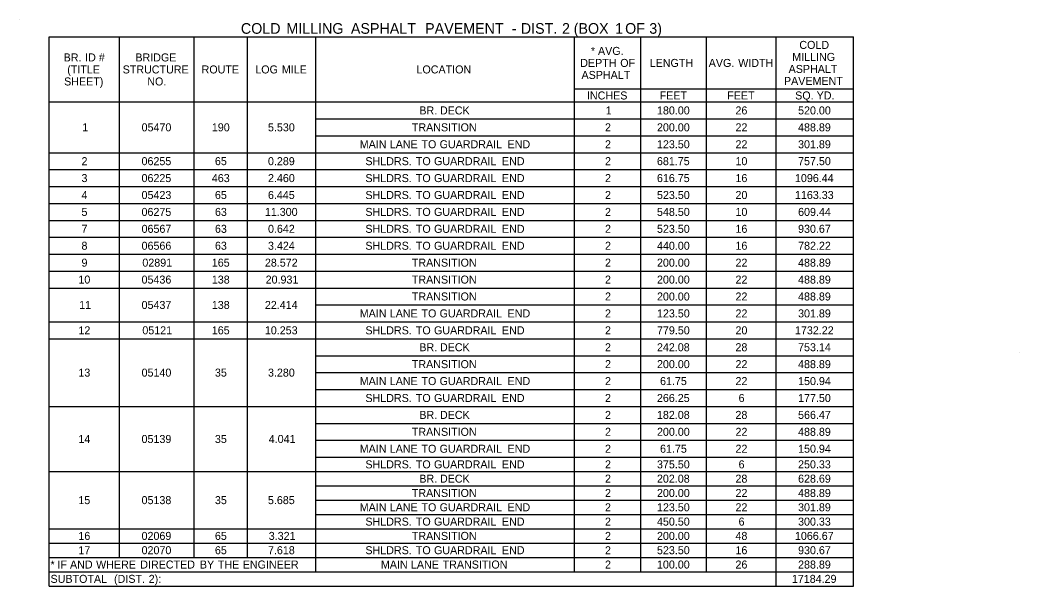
# Model space of a CAD drawing. Extents: x 544250 to 1930787, y -1948365 to 596640.
# Drawn here: x 548053 to 548802, y -1947842 to -1947418 of the extents above; entities that cross this region are included whole.
import ezdxf

# ---------------------------------------------------------------- set-up
doc = ezdxf.new("R2010")
doc.units = 0
doc.layers.add('Default', color=7, linetype='Continuous')

msp = doc.modelspace()

# ---------------------------------------------------------------- linework, layer by layer
at = {"layer": 'Default'}
for p, q in [((548053.38, -1947417.61), (548053.38, -1947417.61)), ((548075.32, -1947430.28), (548678.35, -1947430.28)), ((548075.32, -1947430.28), (548678.35, -1947430.28)), ((548075.32, -1947841.73), (548075.32, -1947430.28)), ((548075.32, -1947841.73), (548075.32, -1947430.28)), ((548127.97, -1947820.28), (548127.97, -1947430.28)), ((548184.03, -1947820.28), (548184.03, -1947430.28)), ((548224, -1947820.28), (548224, -1947430.28)), ((548275.19, -1947831.01), (548275.19, -1947430.28)), ((548469.22, -1947831.01), (548469.22, -1947430.28)), ((548518.94, -1947831.01), (548518.94, -1947430.28)), ((548568.18, -1947831.01), (548568.18, -1947430.28)), ((548620.34, -1947841.73), (548620.34, -1947430.28)), ((548678.35, -1947841.73), (548678.35, -1947430.28)), ((548469.22, -1947469.28), (548568.18, -1947469.28)), ((548469.22, -1947469.28), (548518.94, -1947469.28)), ((548518.94, -1947469.28), (548678.35, -1947469.28)), ((548568.18, -1947479.03), (548568.18, -1947469.28)), ((548075.32, -1947479.03), (548678.35, -1947479.03)), ((548275.19, -1947491.71), (548678.35, -1947491.71)), ((548275.19, -1947504.38), (548678.35, -1947504.38)), ((548075.32, -1947517.06), (548678.35, -1947517.06)), ((548275.19, -1947517.06), (548678.35, -1947517.06)), ((548075.32, -1947529.73), (548678.35, -1947529.73)), ((548469.22, -1947529.73), (548678.35, -1947529.73)), ((548075.32, -1947542.41), (548678.35, -1947542.41)), ((548075.32, -1947555.08), (548678.35, -1947555.08)), ((548075.32, -1947567.76), (548678.35, -1947567.76)), ((548075.32, -1947580.43), (548678.35, -1947580.43)), ((548075.32, -1947593.11), (548678.35, -1947593.11)), ((548075.32, -1947605.78), (548678.35, -1947605.78)), ((548075.32, -1947618.46), (548678.35, -1947618.46)), ((548275.19, -1947631.13), (548678.35, -1947631.13)), ((548075.32, -1947643.81), (548678.35, -1947643.81)), ((548075.32, -1947656.48), (548678.35, -1947656.48)), ((548275.19, -1947669.16), (548678.35, -1947669.16)), ((548802.37, -1947666.61), (548802.37, -1947666.61)), ((548275.19, -1947681.83), (548678.35, -1947681.83)), ((548275.19, -1947694.51), (548678.35, -1947694.51)), ((548518.94, -1947694.51), (548620.34, -1947694.51)), ((548620.34, -1947694.51), (548678.35, -1947694.51)), ((548075.32, -1947707.18), (548678.35, -1947707.18)), ((548275.19, -1947719.86), (548678.35, -1947719.86)), ((548275.19, -1947732.53), (548678.35, -1947732.53)), ((548275.19, -1947745.21), (548678.35, -1947745.21)), ((548518.94, -1947745.21), (548620.34, -1947745.21)), ((548620.34, -1947745.21), (548678.35, -1947745.21)), ((548075.32, -1947755.93), (548678.35, -1947755.93)), ((548275.19, -1947766.66), (548678.35, -1947766.66)), ((548275.19, -1947777.38), (548678.35, -1947777.38)), ((548275.19, -1947788.11), (548678.35, -1947788.11)), ((548275.19, -1947788.11), (548678.35, -1947788.11)), ((548075.32, -1947798.83), (548678.35, -1947798.83)), ((548075.32, -1947809.56), (548275.19, -1947809.56)), ((548275.19, -1947809.56), (548678.35, -1947809.56)), ((548075.32, -1947820.28), (548678.35, -1947820.28)), ((548620.34, -1947820.28), (548678.35, -1947820.28)), ((548075.32, -1947831.01), (548678.35, -1947831.01)), ((548075.32, -1947841.73), (548678.35, -1947841.73))]:
    msp.add_line(p, q, dxfattribs=at)

# ---------------------------------------------------------------- texts
for s, height, p in [('COLD', 8, (548219.01, -1947427.94)), (' MILLING', 8, (548250.12, -1947427.94)), (' ASPHALT', 8, (548298.5, -1947427.94)), (' PAVEMENT', 8, (548354.16, -1947427.94)), (' -', 8, (548419.15, -1947427.94)), (' DIST.', 8, (548425.89, -1947427.94)), (' 2', 8, (548456.79, -1947427.94)), (' (BOX', 8, (548465.55, -1947427.94)), (' 1', 8, (548496.59, -1947427.94)), (' OF', 8, (548504.09, -1947427.94)), (' 3)', 8, (548522.2, -1947427.94)), ('COLD', 6, (548637.68, -1947439.28)), ('*', 6, (548481.41, -1947443.78)), (' AVG.', 6, (548484.49, -1947443.78)), ('BR.', 6, (548086.12, -1947448.66)), (' ID', 6, (548099.98, -1947448.66)), (' #', 6, (548110.27, -1947448.66)), ('BRIDGE', 6, (548139.9, -1947448.66)), ('DEPTH', 6, (548473.4, -1947452.78)), (' OF', 6, (548501.17, -1947452.78)), ('LENGTH', 6, (548525.48, -1947452.78)), ('AVG.', 6, (548569.72, -1947452.78)), (' WIDTH', 6, (548589.64, -1947452.78)), ('MILLING', 6, (548632.37, -1947448.28)), ('(TITLE', 6, (548088.81, -1947457.66)), ('STRUCTURE', 6, (548130.35, -1947457.66)), ('ROUTE', 6, (548189.55, -1947457.66)), ('LOG', 6, (548229.8, -1947457.66)), (' MILE', 6, (548247.46, -1947457.66)), ('LOCATION', 6, (548350.65, -1947457.66)), ('ASPHALT', 6, (548474.37, -1947461.78)), ('ASPHALT', 6, (548629.64, -1947457.28)), ('SHEET)', 6, (548086.48, -1947466.66)), ('NO.', 6, (548148.83, -1947466.66)), ('PAVEMENT', 6, (548626.14, -1947466.28)), ('INCHES', 6, (548478.44, -1947477.16)), ('FEET', 6, (548532.93, -1947477.16)), ('FEET', 6, (548583.63, -1947477.16)), ('SQ.', 6, (548634.55, -1947477.16)), (' YD.', 6, (548648.42, -1947477.16)), ('BR.', 6, (548352.78, -1947488.37)), (' DECK', 6, (548366.02, -1947488.37)), ('1', 6, (548492.52, -1947488.37)), ('180.00', 6, (548530.95, -1947488.37)), ('26', 6, (548589.79, -1947488.37)), ('520.00', 6, (548636.73, -1947488.37)), ('1', 6, (548100.08, -1947501.04)), ('05470', 6, (548144.55, -1947501.04)), ('190', 6, (548197.23, -1947501.04)), ('5.530', 6, (548239.31, -1947501.04)), ('TRANSITION', 6, (548347.16, -1947501.04)), ('2', 6, (548491.97, -1947501.04)), ('200.00', 6, (548530.95, -1947501.04)), ('22', 6, (548589.82, -1947501.04)), ('488.89', 6, (548636.72, -1947501.04)), ('MAIN', 6, (548308.11, -1947513.72)), (' LANE', 6, (548328.39, -1947513.72)), (' TO', 6, (548352.17, -1947513.72)), (' GUARDRAIL', 6, (548365.76, -1947513.72)), (' END', 6, (548416.71, -1947513.72)), ('2', 6, (548491.97, -1947513.72)), ('123.50', 6, (548530.95, -1947513.72)), ('22', 6, (548589.82, -1947513.72)), ('301.89', 6, (548636.72, -1947513.72)), ('2', 6, (548099.53, -1947526.39)), ('06255', 6, (548144.51, -1947526.39)), ('65', 6, (548199.52, -1947526.39)), ('0.289', 6, (548239.3, -1947526.39)), ('SHLDRS.', 6, (548312.34, -1947526.39)), (' TO', 6, (548347.94, -1947526.39)), (' GUARDRAIL', 6, (548361.54, -1947526.39)), (' END', 6, (548412.49, -1947526.39)), ('2', 6, (548491.97, -1947526.39)), ('681.75', 6, (548530.91, -1947526.39)), ('10', 6, (548589.8, -1947526.39)), ('757.50', 6, (548636.73, -1947526.39)), ('3', 6, (548099.5, -1947539.07)), ('06225', 6, (548144.51, -1947539.07)), ('463', 6, (548197.22, -1947539.07)), ('2.460', 6, (548239.31, -1947539.07)), ('SHLDRS.', 6, (548312.34, -1947539.07)), (' TO', 6, (548347.94, -1947539.07)), (' GUARDRAIL', 6, (548361.54, -1947539.07)), (' END', 6, (548412.49, -1947539.07)), ('2', 6, (548491.97, -1947539.07)), ('616.75', 6, (548530.91, -1947539.07)), ('16', 6, (548589.79, -1947539.07)), ('1096.44', 6, (548634.41, -1947539.07)), ('4', 6, (548099.51, -1947551.74)), ('05423', 6, (548144.54, -1947551.74)), ('65', 6, (548199.52, -1947551.74)), ('6.445', 6, (548239.28, -1947551.74)), ('SHLDRS.', 6, (548312.34, -1947551.74)), (' TO', 6, (548347.94, -1947551.74)), (' GUARDRAIL', 6, (548361.54, -1947551.74)), (' END', 6, (548412.49, -1947551.74)), ('2', 6, (548491.97, -1947551.74)), ('523.50', 6, (548530.95, -1947551.74)), ('20', 6, (548589.8, -1947551.74)), ('1163.33', 6, (548634.39, -1947551.74)), ('5', 6, (548099.48, -1947564.42)), ('06275', 6, (548144.51, -1947564.42)), ('63', 6, (548199.55, -1947564.42)), ('11.300', 6, (548236.98, -1947564.42)), ('SHLDRS.', 6, (548312.34, -1947564.42)), (' TO', 6, (548347.94, -1947564.42)), (' GUARDRAIL', 6, (548361.54, -1947564.42)), (' END', 6, (548412.49, -1947564.42)), ('2', 6, (548491.97, -1947564.42)), ('548.50', 6, (548530.95, -1947564.42)), ('10', 6, (548589.8, -1947564.42)), ('609.44', 6, (548636.74, -1947564.42)), ('7', 6, (548099.5, -1947577.09)), ('06567', 6, (548144.54, -1947577.09)), ('63', 6, (548199.55, -1947577.09)), ('0.642', 6, (548239.33, -1947577.09)), ('SHLDRS.', 6, (548312.34, -1947577.09)), (' TO', 6, (548347.94, -1947577.09)), (' GUARDRAIL', 6, (548361.54, -1947577.09)), (' END', 6, (548412.49, -1947577.09)), ('2', 6, (548491.97, -1947577.09)), ('523.50', 6, (548530.95, -1947577.09)), ('16', 6, (548589.79, -1947577.09)), ('930.67', 6, (548636.72, -1947577.09)), ('8', 6, (548099.5, -1947589.77)), ('06566', 6, (548144.54, -1947589.77)), ('63', 6, (548199.55, -1947589.77)), ('3.424', 6, (548239.32, -1947589.77)), ('SHLDRS.', 6, (548312.34, -1947589.77)), (' TO', 6, (548347.94, -1947589.77)), (' GUARDRAIL', 6, (548361.54, -1947589.77)), (' END', 6, (548412.49, -1947589.77)), ('2', 6, (548491.97, -1947589.77)), ('440.00', 6, (548530.95, -1947589.77)), ('16', 6, (548589.79, -1947589.77)), ('782.22', 6, (548636.75, -1947589.77)), ('9', 6, (548099.5, -1947602.44)), ('02891', 6, (548145.12, -1947602.44)), ('165', 6, (548197.19, -1947602.44)), ('28.572', 6, (548237, -1947602.44)), ('TRANSITION', 6, (548347.16, -1947602.44)), ('2', 6, (548491.97, -1947602.44)), ('200.00', 6, (548530.95, -1947602.44)), ('22', 6, (548589.82, -1947602.44)), ('488.89', 6, (548636.72, -1947602.44)), ('10', 6, (548097.18, -1947615.12)), ('05436', 6, (548144.54, -1947615.12)), ('138', 6, (548197.21, -1947615.12)), ('20.931', 6, (548237.55, -1947615.12)), ('TRANSITION', 6, (548347.16, -1947615.12)), ('2', 6, (548491.97, -1947615.12)), ('200.00', 6, (548530.95, -1947615.12)), ('22', 6, (548589.82, -1947615.12)), ('488.89', 6, (548636.72, -1947615.12)), ('11', 6, (548097.75, -1947634.13)), ('05437', 6, (548144.54, -1947634.13)), ('138', 6, (548197.21, -1947634.13)), ('22.414', 6, (548236.99, -1947634.13)), ('TRANSITION', 6, (548347.16, -1947627.79)), ('2', 6, (548491.97, -1947627.79)), ('200.00', 6, (548530.95, -1947627.79)), ('22', 6, (548589.82, -1947627.79)), ('488.89', 6, (548636.72, -1947627.79)), ('MAIN', 6, (548308.11, -1947640.47)), (' LANE', 6, (548328.39, -1947640.47)), (' TO', 6, (548352.17, -1947640.47)), (' GUARDRAIL', 6, (548365.76, -1947640.47)), (' END', 6, (548416.71, -1947640.47)), ('2', 6, (548491.97, -1947640.47)), ('123.50', 6, (548530.95, -1947640.47)), ('22', 6, (548589.82, -1947640.47)), ('301.89', 6, (548636.72, -1947640.47)), ('12', 6, (548097.2, -1947653.14)), ('05121', 6, (548145.12, -1947653.14)), ('165', 6, (548197.19, -1947653.14)), ('10.253', 6, (548236.97, -1947653.14)), ('SHLDRS.', 6, (548312.34, -1947653.14)), (' TO', 6, (548347.94, -1947653.14)), (' GUARDRAIL', 6, (548361.54, -1947653.14)), (' END', 6, (548412.49, -1947653.14)), ('2', 6, (548491.97, -1947653.14)), ('779.50', 6, (548530.95, -1947653.14)), ('20', 6, (548589.8, -1947653.14)), ('1732.22', 6, (548634.42, -1947653.14)), ('BR.', 6, (548352.78, -1947665.82)), (' DECK', 6, (548366.02, -1947665.82)), ('2', 6, (548491.97, -1947665.82)), ('242.08', 6, (548530.93, -1947665.82)), ('28', 6, (548589.78, -1947665.82)), ('753.14', 6, (548636.74, -1947665.82)), ('TRANSITION', 6, (548347.16, -1947678.49)), ('2', 6, (548491.97, -1947678.49)), ('200.00', 6, (548530.95, -1947678.49)), ('22', 6, (548589.82, -1947678.49)), ('488.89', 6, (548636.72, -1947678.49)), ('13', 6, (548097.17, -1947684.83)), ('05140', 6, (548144.55, -1947684.83)), ('35', 6, (548199.52, -1947684.83)), ('3.280', 6, (548239.31, -1947684.83)), ('MAIN', 6, (548308.11, -1947691.17)), (' LANE', 6, (548328.39, -1947691.17)), (' TO', 6, (548352.17, -1947691.17)), (' GUARDRAIL', 6, (548365.76, -1947691.17)), (' END', 6, (548416.71, -1947691.17)), ('2', 6, (548491.97, -1947691.17)), ('61.75', 6, (548533.24, -1947691.17)), ('22', 6, (548589.82, -1947691.17)), ('150.94', 6, (548636.74, -1947691.17)), ('SHLDRS.', 6, (548312.34, -1947703.84)), (' TO', 6, (548347.94, -1947703.84)), (' GUARDRAIL', 6, (548361.54, -1947703.84)), (' END', 6, (548412.49, -1947703.84)), ('2', 6, (548491.97, -1947703.84)), ('266.25', 6, (548530.91, -1947703.84)), ('6', 6, (548592.12, -1947703.84)), ('177.50', 6, (548636.73, -1947703.84)), ('BR.', 6, (548352.78, -1947716.52)), (' DECK', 6, (548366.02, -1947716.52)), ('2', 6, (548491.97, -1947716.52)), ('182.08', 6, (548530.93, -1947716.52)), ('28', 6, (548589.78, -1947716.52)), ('566.47', 6, (548636.72, -1947716.52)), ('TRANSITION', 6, (548347.16, -1947729.19)), ('2', 6, (548491.97, -1947729.19)), ('200.00', 6, (548530.95, -1947729.19)), ('22', 6, (548589.82, -1947729.19)), ('488.89', 6, (548636.72, -1947729.19)), ('14', 6, (548097.18, -1947734.56)), ('05139', 6, (548144.53, -1947734.56)), ('35', 6, (548199.52, -1947734.56)), ('4.041', 6, (548239.88, -1947734.56)), ('MAIN', 6, (548308.11, -1947741.87)), (' LANE', 6, (548328.39, -1947741.87)), (' TO', 6, (548352.17, -1947741.87)), (' GUARDRAIL', 6, (548365.76, -1947741.87)), (' END', 6, (548416.71, -1947741.87)), ('2', 6, (548491.97, -1947741.87)), ('61.75', 6, (548533.24, -1947741.87)), ('22', 6, (548589.82, -1947741.87)), ('150.94', 6, (548636.74, -1947741.87)), ('SHLDRS.', 6, (548312.34, -1947753.57)), (' TO', 6, (548347.94, -1947753.57)), (' GUARDRAIL', 6, (548361.54, -1947753.57)), (' END', 6, (548412.49, -1947753.57)), ('2', 6, (548491.97, -1947753.57)), ('375.50', 6, (548530.95, -1947753.57)), ('6', 6, (548592.12, -1947753.57)), ('250.33', 6, (548636.72, -1947753.57)), ('BR.', 6, (548352.78, -1947764.29)), (' DECK', 6, (548366.02, -1947764.29)), ('2', 6, (548491.97, -1947764.29)), ('202.08', 6, (548530.93, -1947764.29)), ('28', 6, (548589.78, -1947764.29)), ('628.69', 6, (548636.72, -1947764.29)), ('TRANSITION', 6, (548347.16, -1947775.02)), ('2', 6, (548491.97, -1947775.02)), ('200.00', 6, (548530.95, -1947775.02)), ('22', 6, (548589.82, -1947775.02)), ('488.89', 6, (548636.72, -1947775.02)), ('15', 6, (548097.15, -1947780.38)), ('05138', 6, (548144.53, -1947780.38)), ('35', 6, (548199.52, -1947780.38)), ('5.685', 6, (548239.28, -1947780.38)), ('MAIN', 6, (548308.11, -1947785.74)), (' LANE', 6, (548328.39, -1947785.74)), (' TO', 6, (548352.17, -1947785.74)), (' GUARDRAIL', 6, (548365.76, -1947785.74)), (' END', 6, (548416.71, -1947785.74)), ('2', 6, (548491.97, -1947785.74)), ('123.50', 6, (548530.95, -1947785.74)), ('22', 6, (548589.82, -1947785.74)), ('301.89', 6, (548636.72, -1947785.74)), ('SHLDRS.', 6, (548312.34, -1947796.47)), (' TO', 6, (548347.94, -1947796.47)), (' GUARDRAIL', 6, (548361.54, -1947796.47)), (' END', 6, (548412.49, -1947796.47)), ('2', 6, (548491.97, -1947796.47)), ('450.50', 6, (548530.95, -1947796.47)), ('6', 6, (548592.12, -1947796.47)), ('300.33', 6, (548636.72, -1947796.47)), ('16', 6, (548097.17, -1947807.19)), ('02069', 6, (548144.53, -1947807.19)), ('65', 6, (548199.52, -1947807.19)), ('3.321', 6, (548239.88, -1947807.19)), ('TRANSITION', 6, (548347.16, -1947807.19)), ('2', 6, (548491.97, -1947807.19)), ('200.00', 6, (548530.95, -1947807.19)), ('48', 6, (548589.78, -1947807.19)), ('1066.67', 6, (548634.39, -1947807.19)), ('17', 6, (548097.17, -1947817.92)), ('02070', 6, (548144.55, -1947817.92)), ('65', 6, (548199.52, -1947817.92)), ('7.618', 6, (548239.3, -1947817.92)), ('SHLDRS.', 6, (548312.34, -1947817.92)), (' TO', 6, (548347.94, -1947817.92)), (' GUARDRAIL', 6, (548361.54, -1947817.92)), (' END', 6, (548412.49, -1947817.92)), ('2', 6, (548491.97, -1947817.92)), ('523.50', 6, (548530.95, -1947817.92)), ('16', 6, (548589.79, -1947817.92)), ('930.67', 6, (548636.72, -1947817.92)), ('*', 6, (548076.29, -1947828.64)), (' IF', 6, (548079.26, -1947828.64)), (' AND', 6, (548088.65, -1947828.64)), (' WHERE', 6, (548108.23, -1947828.64)), (' DIRECTED', 6, (548141.32, -1947828.64)), (' BY', 6, (548186.06, -1947828.64)), (' THE', 6, (548199.51, -1947828.64)), (' ENGINEER', 6, (548218.15, -1947828.64)), ('MAIN', 6, (548323.97, -1947828.64)), (' LANE', 6, (548344.24, -1947828.64)), (' TRANSITION', 6, (548368.02, -1947828.64)), ('2', 6, (548491.97, -1947828.64)), ('100.00', 6, (548530.95, -1947828.64)), ('26', 6, (548589.79, -1947828.64)), ('288.89', 6, (548636.72, -1947828.64)), ('SUBTOTAL', 6, (548076.29, -1947839.37)), (' (DIST.', 6, (548121.68, -1947839.37)), (' 2):', 6, (548147.65, -1947839.37)), ('17184.29', 6, (548632.07, -1947839.37))]:
    msp.add_text(s, height=height, dxfattribs=at).set_placement(p)

doc.saveas('drawing.dxf')
